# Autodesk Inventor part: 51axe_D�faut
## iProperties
Created: 2011-01
Part Number: 51axe_D�faut
Document SubType Name: Modeling
Designer: eric
Density: 1 g/cm^3
Mass: 54.2276 g
Surface Area: 186.426 cm^2
Volume: 54.2276 cm^3
Author: eric
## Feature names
1. Base1
